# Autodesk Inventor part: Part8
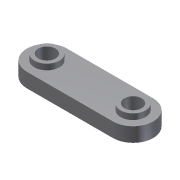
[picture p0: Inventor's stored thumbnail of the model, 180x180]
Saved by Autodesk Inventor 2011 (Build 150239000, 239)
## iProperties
Shininess: 77.0
Length Units: 11269
Angle Units: 11279
Time Units: 11290
Mass Units: 11283
Length Display Precision: 3
Angle Display Precision: 2
Created: 2002-01
Part Number: Part8
Document SubType Name: Modeling
Designer: ***
Density: 1 g/cm^3
Density: 0.0
Volumn: 0.0
Area: 0.0
PropertySet Name: Model Information
Control State: 0
Master: False
Checked Out: False
Author: ***
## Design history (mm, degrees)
sketch "Sketch1"
  geometry: L1 (-33.118, 12.346)-(26.882, 12.361); L2 (-33.111, -15.654)-(26.889, -15.639); C1 r 6 at (-33.114, -1.654); C2 r 6 at (26.886, -1.639); A1 r 14 centre (-33.114, -1.654) between (-33.118, 12.346) and (-33.111, -15.654); A2 r 14 centre (26.886, -1.639) between (26.889, -15.639) and (26.882, 12.361)
  constraints: 4 centre point, 4 end point, 4 point on circle, 4 tangent, 2 coincident, 2 equal radius
  dimensions: "d0" = 60 distance of L1.start L1.end; "d1" = 14 radius of A1; "d2" = 12 diameter of C1
extrude "Extrusion1" new body sketch "Sketch1" distance "d3" = 10; taper "d4" = 0 deg
sketch "Sketch2"
  geometry: C1 r 6 at (26.886, -1.639) reference; C2 r 6 at (-33.114, -1.654) reference; C3 r 8.694 at (-33.114, -1.654); C4 r 8.694 at (26.886, -1.639)
  constraints: 2 centre point, 2 coincident, 1 equal radius
extrude "Extrusion2" join sketch "Sketch2" distance "d5" = 4; taper "d6" = 0 deg
body "Solid1"
